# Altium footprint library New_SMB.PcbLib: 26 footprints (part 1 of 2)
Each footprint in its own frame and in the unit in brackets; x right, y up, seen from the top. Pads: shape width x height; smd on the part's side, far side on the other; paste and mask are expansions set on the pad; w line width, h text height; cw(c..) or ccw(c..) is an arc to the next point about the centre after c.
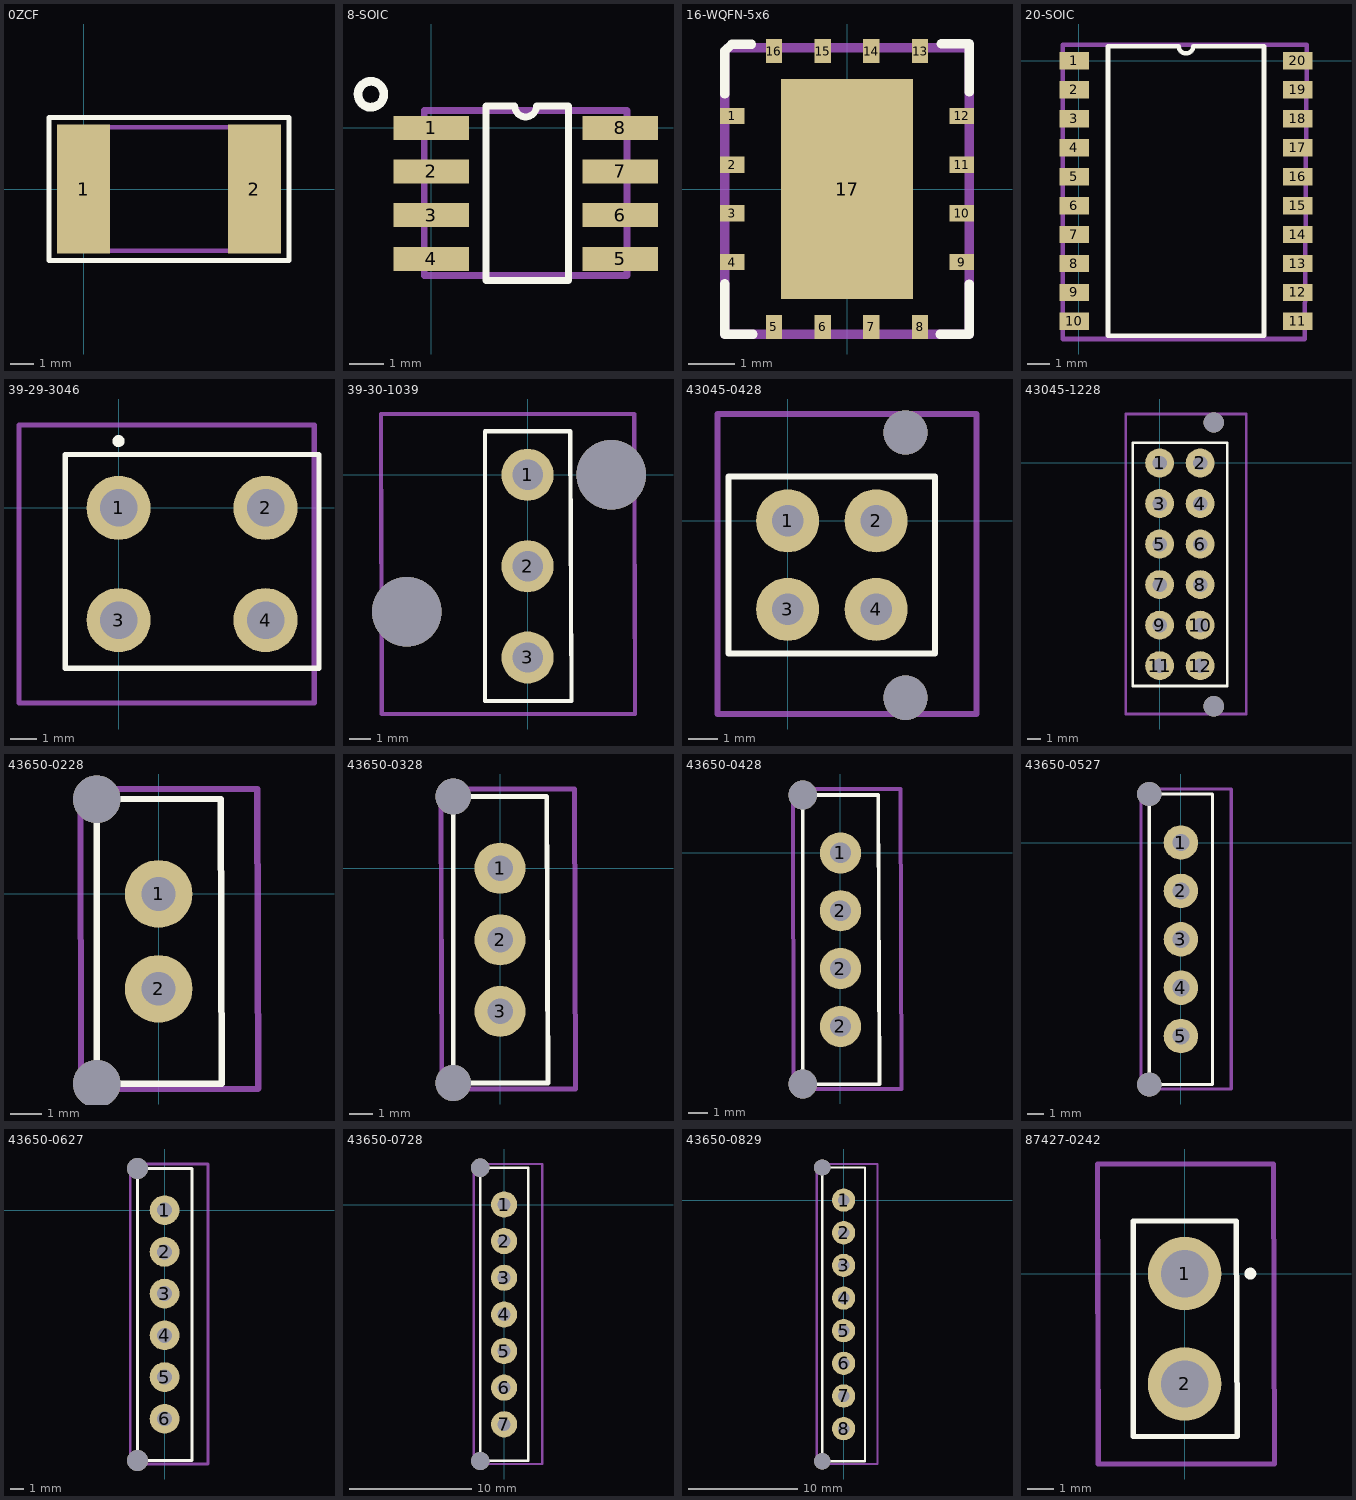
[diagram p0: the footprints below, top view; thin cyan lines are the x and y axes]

## 0ZCF [mm]
pads (2):
  rect 2.3x5.6 smd: 1(0,0) 2(7.4,0)
Top Overlay:
  lines w0.2: -1.5,-3.1 8.9,-3.1 8.9,3.1 -1.5,3.1 -1.5,-3.1
Mechanical 1:
  lines w0.2: -0.175,-2.675 7.575,-2.675 7.575,2.675 -0.175,2.675 -0.175,-2.675
  text ".Designator" at 3.842,-2.025 h0.4
3D body "0ZCF0100AF2A.stp": height 1.02, standoff -0.03, extent -0.1,-2.65 7.5,2.65

## 8-SOIC [mm]
pads (8):
  rect 2.2x0.7 smd: 1(0,0) 2(0,-1.27) 3(0,-2.54) 4(0,-3.81) 5(5.5,-3.81) 6(5.5,-2.54) 7(5.5,-1.27) 8(5.5,0)
Top Overlay:
  lines w0.2: 1.6,-4.445 4,-4.445 4,0.635 3.067,0.635 cw(c2.75,0.635) 2.432,0.635 1.6,0.635 1.6,-4.445
  lines w0.254: -1.375,0.952 cw(c-1.75,0.975) -1.374,0.975
Mechanical 1:
  lines w0.2: -0.2,-4.3 5.7,-4.3 5.7,0.5 -0.2,0.5 -0.2,-4.3
  text ".Designator" at 2.867,-4 h0.4
3D body "SOIC-8.SLDPRT": height 1.5, standoff 0, extent -0.19,-4.35 5.79,0.55

## 16-WQFN-5x6 [mm]
pads (17):
  rect 0.52x0.35 smd mask+0.05: 1(-2.475,1.575) 2(-2.475,0.525) 3(-2.475,-0.525) 4(-2.475,-1.575) 9(2.475,-1.575) 10(2.475,-0.525) 11(2.475,0.525) 12(2.475,1.575)
  rect 0.35x0.52 smd mask+0.05: 5(-1.575,-2.975) 6(-0.525,-2.975) 7(0.525,-2.975) 8(1.575,-2.975) 13(1.575,2.975) 14(0.525,2.975) 15(-0.525,2.975) 16(-1.575,2.975)
  rect 2.85x4.75 smd mask+0.05: 17(0,0)
Top Overlay:
  lines w0.2: -2.635,-2.043 -2.635,-3.135 -2.027,-3.135 ; -2.635,2.051 -2.635,2.975 -2.488,3.122 -2.06,3.122 ; 2.004,-3.135 2.635,-3.135 2.635,-2.051 ; 2.032,3.135 2.635,3.135 2.635,2.092
  text "." at -3.3,1.5 h1
Mechanical 1:
  lines w0.2: -2.635,2.975 -2.635,-3.135 2.635,-3.135 2.635,2.962 2.549,3.049 -2.561,3.049
  text ".Designator" at -1.683,-1.975 h0.4
3D body: height 0.8, standoff 0.05, extent -2.635,-3.135 2.635,3.135

## 20-SOIC [mm]
pads (20):
  rect 1.3x0.762 smd: 1(-0.2,0) 2(-0.2,-1.27) 3(-0.2,-2.54) 4(-0.2,-3.81) 5(-0.2,-5.08) 6(-0.2,-6.35) 7(-0.2,-7.62) 8(-0.2,-8.89) 9(-0.2,-10.16) 10(-0.2,-11.43) 11(9.598,-11.43) 12(9.598,-10.16) 13(9.598,-8.89) 14(9.598,-7.62) 15(9.598,-6.35) 16(9.598,-5.08) 17(9.598,-3.81) 18(9.598,-2.54) 19(9.598,-1.27) 20(9.598,0)
Top Overlay:
  lines w0.2: 1.279,-12.065 1.279,0.635 4.381,0.635 ccw(c4.699,0.635) 5.016,0.635 8.119,0.635 8.119,-12.065 1.279,-12.065
Mechanical 1:
  lines w0.2: -0.7,-12.2 9.9,-12.2 10,0.7 -0.7,0.7 -0.7,-12.2
  text ".Designator" at 7.367,-11.5 h1
3D body "SO-20_SW_LIT.step": height 2.64, standoff 0, extent -0.642,-12.239 10,0.765

## 39-29-3046 [mm]
pads (4):
  round 2.4 hole 1.4: 1(0,0) 2(5.5,0) 3(0,-4.2) 4(5.5,-4.2)
Top Overlay:
  circle w0.254: c0,2.5 r0.1
  lines w0.2: -2,-6 7.5,-6 7.5,2 -2,2 -2,-6
Mechanical 1:
  lines w0.2: -3.725,-7.3 7.325,-7.3 7.325,3.1 -3.725,3.1 -3.725,-7.3
  text ".Designator" at -2.6,-6.9 h0.75
3D body "0039293046.stp": height 12.8, standoff -3.5, extent -3.7,-7.3 7.3,3.1

## 39-30-1039 [mm]
pads (3):
  round 2.4 hole 1.4: 1(0,0) 2(0,-4.2) 3(0,-8.4)
via 3.85,0 diameter 3.2 hole 3.2
via -5.55,-6.3 diameter 3.2 hole 3.2
Top Overlay:
  lines w0.2: -1.96,-10.4 2.02,-10.4 1.964,2 -1.96,2 -1.96,-10.4
Mechanical 1:
  lines w0.2: -6.741,2.8 4.9,2.8 4.941,-11 -6.711,-11 -6.741,2.8
  text ".Designator" at -2.833,-10.2 h1
3D body "0039301039.stp": height 12.45, standoff -3.5, extent -6.679,-11.1 4.879,2.7

## 43045-0428 [mm]
pads (4):
  round 2.14 hole 1.07: 1(0,0) 2(3,0) 3(0,-3) 4(3,-3)
via 4,-6 diameter 1.5 hole 1.5
via 4,3 diameter 1.5 hole 1.5
Top Overlay:
  lines w0.2: -2,-4.5 -2,1.5 5,1.5 5,-4.5 -2,-4.5
Mechanical 1:
  lines w0.2: -2.375,-6.55 6.4,-6.55 6.4,3.625 -2.375,3.625 -2.375,-6.55
  text ".Designator" at 5.755,-5.93 h0.9
3D body "430450428.stp": height 9.95, standoff -3.14, extent -2.37,-6.575 6.4,3.575

## 43045-1228 [mm]
pads (12):
  round 2.14 hole 1.07: 1(0,0) 2(3,0) 3(0,-3) 4(3,-3) 5(0,-6) 6(3,-6) 7(0,-9) 8(3,-9) 9(0,-12) 10(3,-12) 11(0,-15) 12(3,-15)
via 4,3 diameter 1.5 hole 1.5
via 4,-18 diameter 1.5 hole 1.5
Top Overlay:
  lines w0.2: -2,-16.5 -2,1.5 5,1.5 5,-16.5 -2,-16.5
Mechanical 1:
  lines w0.2: -2.5,-18.575 6.4,-18.575 6.4,3.625 -2.5,3.625 -2.5,-18.575
  text ".Designator" at 5.773,-17.361 h1
3D body "430451228.stp": height 9.95, standoff -3.14, extent -2.47,-18.575 6.3,3.575

## 43650-0228 [mm]
pads (2):
  round 2.14 hole 1.07: 1(0,0) 2(0,-3)
via -1.96,-6 diameter 1.5 hole 1.5
via -1.96,3 diameter 1.5 hole 1.5
Top Overlay:
  lines w0.2: 1.96,-6 -1.96,-6 -1.96,3 1.96,3 2,-6
Mechanical 1:
  lines w0.2: -2.452,-6.168 -2.472,3.299 -2.491,3.318 3.12,3.318 3.148,-6.151 ; -2.438,-6.168 3.133,-6.168
  text ".Designator" at 2.434,-5.65 h0.8
3D body "436500228.stp": height 10, standoff -3.18, extent -2.51,-6.325 3.06,3.325

## 43650-0328 [mm]
pads (3):
  round 2.14 hole 1.07: 1(0,0) 2(0,-3) 3(0,-6)
via -1.96,3 diameter 1.5 hole 1.5
via -1.96,-9 diameter 1.5 hole 1.5
Top Overlay:
  lines w0.2: -1.96,-9 2.013,-9 1.96,3 -1.96,3 -1.96,-9
Mechanical 1:
  lines w0.2: -2.491,3.318 3.12,3.318 3.157,-9.25 -2.445,-9.25 -2.472,3.299 -2.491,3.318
  text ".Designator" at 1.967,-8.3 h1
3D body "436500328.stp": height 10, standoff -3.18, extent -2.413,-9.25 3.157,3.4

## 43650-0428 [mm]
pads (4):
  round 2.14 hole 1.07: 1(0,0) 2(0,-9) 2(0,-6) 2(0,-3)
via -1.96,3 diameter 1.5 hole 1.5
via -1.96,-12 diameter 1.5 hole 1.5
Top Overlay:
  lines w0.2: -1.96,-12 2.027,-12 1.96,3 -1.96,3 -1.96,-12
Mechanical 1:
  lines w0.2: -2.491,3.318 3.12,3.318 3.166,-12.25 -2.439,-12.25 -2.472,3.299 -2.491,3.318
  text ".Designator" at 1.967,-11.3 h1
3D body "436500428.stp": height 10, standoff -3.18, extent -2.427,-12.291 3.143,3.359

## 43650-0527 [mm]
pads (5):
  round 2.14 hole 1.07: 1(0,0) 2(0,-3) 3(0,-6) 4(0,-9) 5(0,-12)
via -1.96,3 diameter 1.5 hole 1.5
via -1.96,-15 diameter 1.5 hole 1.5
Top Overlay:
  lines w0.2: -1.96,-15 1.96,-15 1.96,3 -1.96,3 -1.96,-15
Mechanical 1:
  lines w0.2: 3.118,-15.279 3.113,-15.284 -2.458,-15.284 -2.472,-15.269 -2.472,3.299 -2.491,3.318 3.12,3.318 3.12,-15.276
  text ".Designator" at 1.967,-14.3 h1
3D body "436500527.STEP": height 9.9, standoff -3.18, extent -2.47,-15.32 3.135,3.32

## 43650-0627 [mm]
pads (6):
  round 2.14 hole 1.07: 1(0,0) 2(0,-3) 3(0,-6) 4(0,-9) 5(0,-12) 6(0,-15)
via -1.96,-18 diameter 1.5 hole 1.5
via -1.96,3 diameter 1.5 hole 1.5
Top Overlay:
  lines w0.2: -1.96,-18 1.96,-18 1.96,3 -1.96,3 -1.96,-18
Mechanical 1:
  lines w0.2: -2.491,3.318 3.12,3.318 3.12,-18.25 -2.472,-18.25 -2.472,3.299 -2.491,3.318
  text ".Designator" at 1.967,-17.3 h1
3D body "436500627.stp": height 10, standoff -3.18, extent -2.45,-18.286 3.12,3.354

## 43650-0728 [mm]
pads (7):
  round 2.14 hole 1.07: 1(0,0) 2(0,-3) 3(0,-6) 4(0,-9) 5(0,-12) 6(0,-15) 7(0,-18)
via -1.96,3 diameter 1.5 hole 1.5
via -1.96,-21 diameter 1.5 hole 1.5
Top Overlay:
  lines w0.2: -1.96,-21 -1.96,3 1.96,3 1.96,-21 -1.96,-21
Mechanical 1:
  lines w0.2: -2.491,3.318 -2.472,3.299 -2.472,-21.25 3.12,-21.25 3.12,3.318 -2.491,3.318
  text ".Designator" at 1.967,-20.3 h1
3D body "436500728.stp": height 10, standoff -3.18, extent -2.47,-21.32 3.1,3.32

## 43650-0829 [mm]
pads (8):
  round 2.14 hole 1.07: 1(0,0) 2(0,-3) 3(0,-6) 4(0,-9) 5(0,-12) 6(0,-15) 7(0,-18) 8(0,-21)
via -1.96,3 diameter 1.5 hole 1.5
via -1.96,-24 diameter 1.5 hole 1.5
Top Overlay:
  lines w0.2: -1.96,-24 -1.96,3 1.96,3 1.96,-24 -1.96,-24
Mechanical 1:
  lines w0.2: -2.491,3.318 -2.472,3.299 -2.472,-24.25 3.12,-24.25 3.12,3.318 -2.491,3.318
  text ".Designator" at 1.967,-23.3 h1
3D body "436500829.stp": height 10, standoff -3.18, extent -2.47,-24.32 3.1,3.32

## 87427-0242 [mm]
pads (2):
  round 2.8 hole 1.8: 1(0,0) 2(0,-4.2)
Top Overlay:
  circle w0.254: c2.5,0 r0.1
  lines w0.2: -1.96,-6.2 -1.96,2 1.964,2 2.001,-6.2 -1.96,-6.2
Mechanical 1:
  lines w0.2: -3.315,4.175 -3.291,-7.25 3.416,-7.25 3.383,4.175 -3.315,4.175
  text ".Designator" at 2.667,-6.6 h1
3D body "0874270242.stp": height 13.5, standoff -3.3, extent -3.2,-7.2 3.4,4.2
